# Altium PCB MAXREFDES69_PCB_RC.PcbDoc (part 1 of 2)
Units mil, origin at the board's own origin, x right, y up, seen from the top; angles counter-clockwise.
Board outline 2598.42 x 2244.09 mil, 6 copper layers (Top Layer, Mid-Layer 1, Mid-Layer 2, Mid-Layer 3, Mid-Layer 4, Bottom Layer); 103 components, 84 nets, 415 pads, 171 vias.
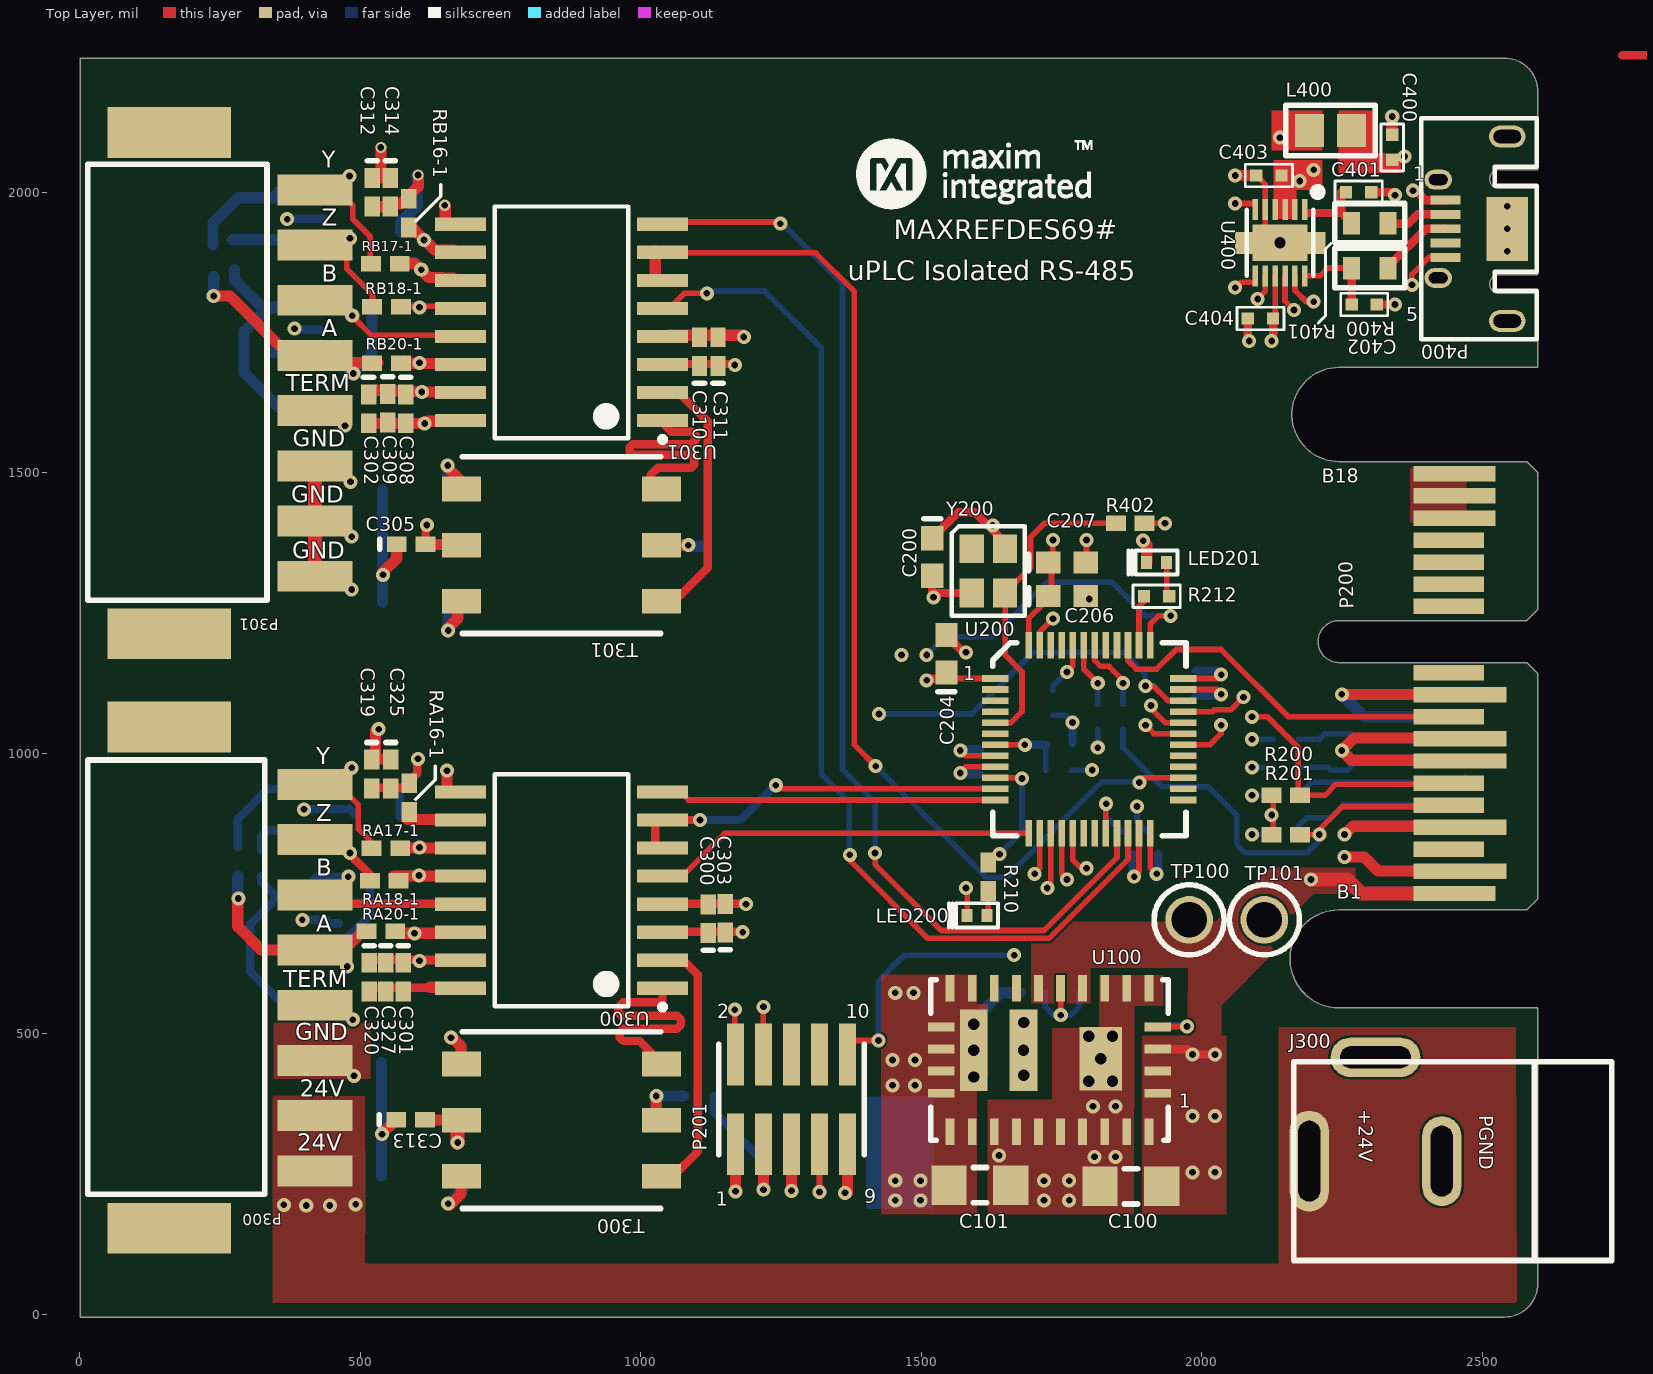
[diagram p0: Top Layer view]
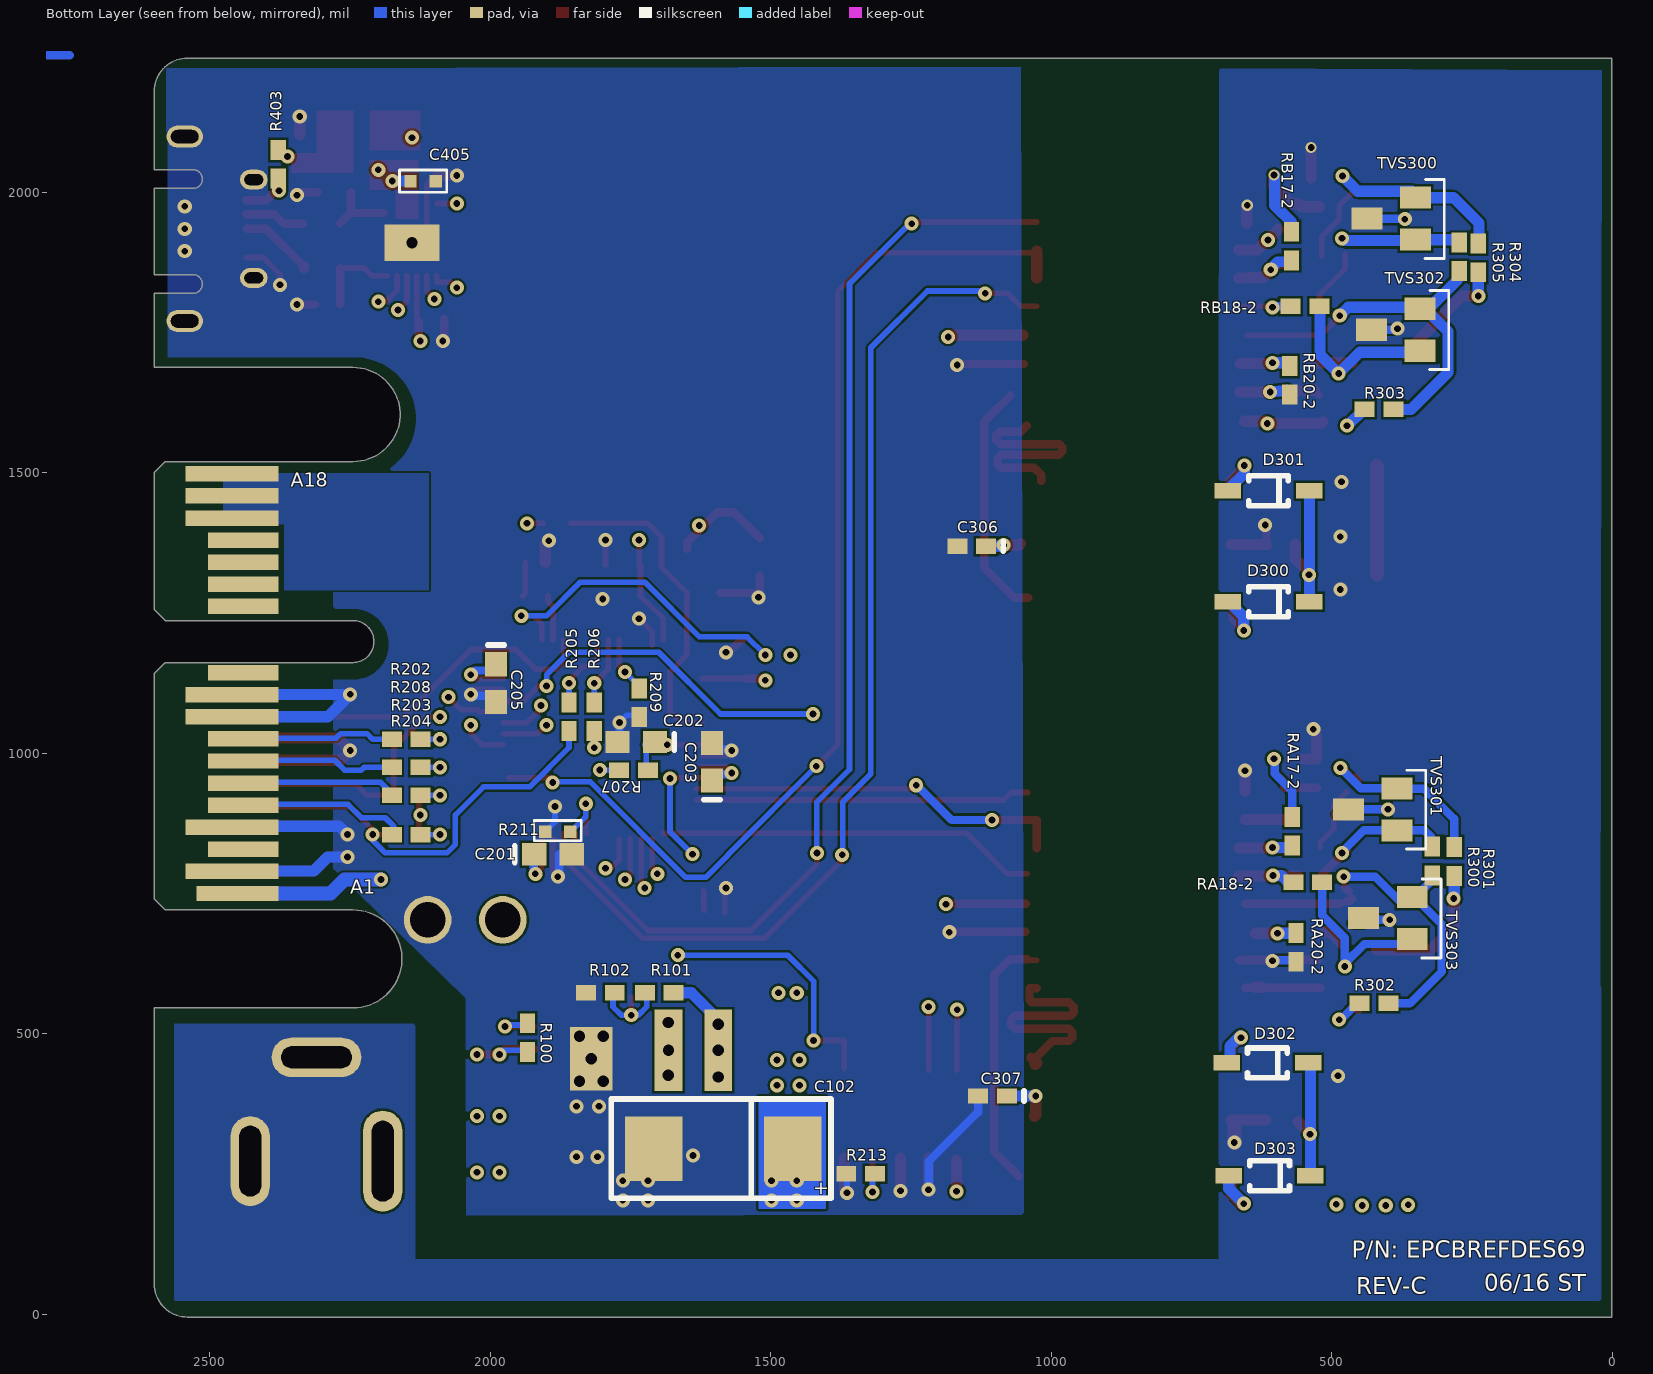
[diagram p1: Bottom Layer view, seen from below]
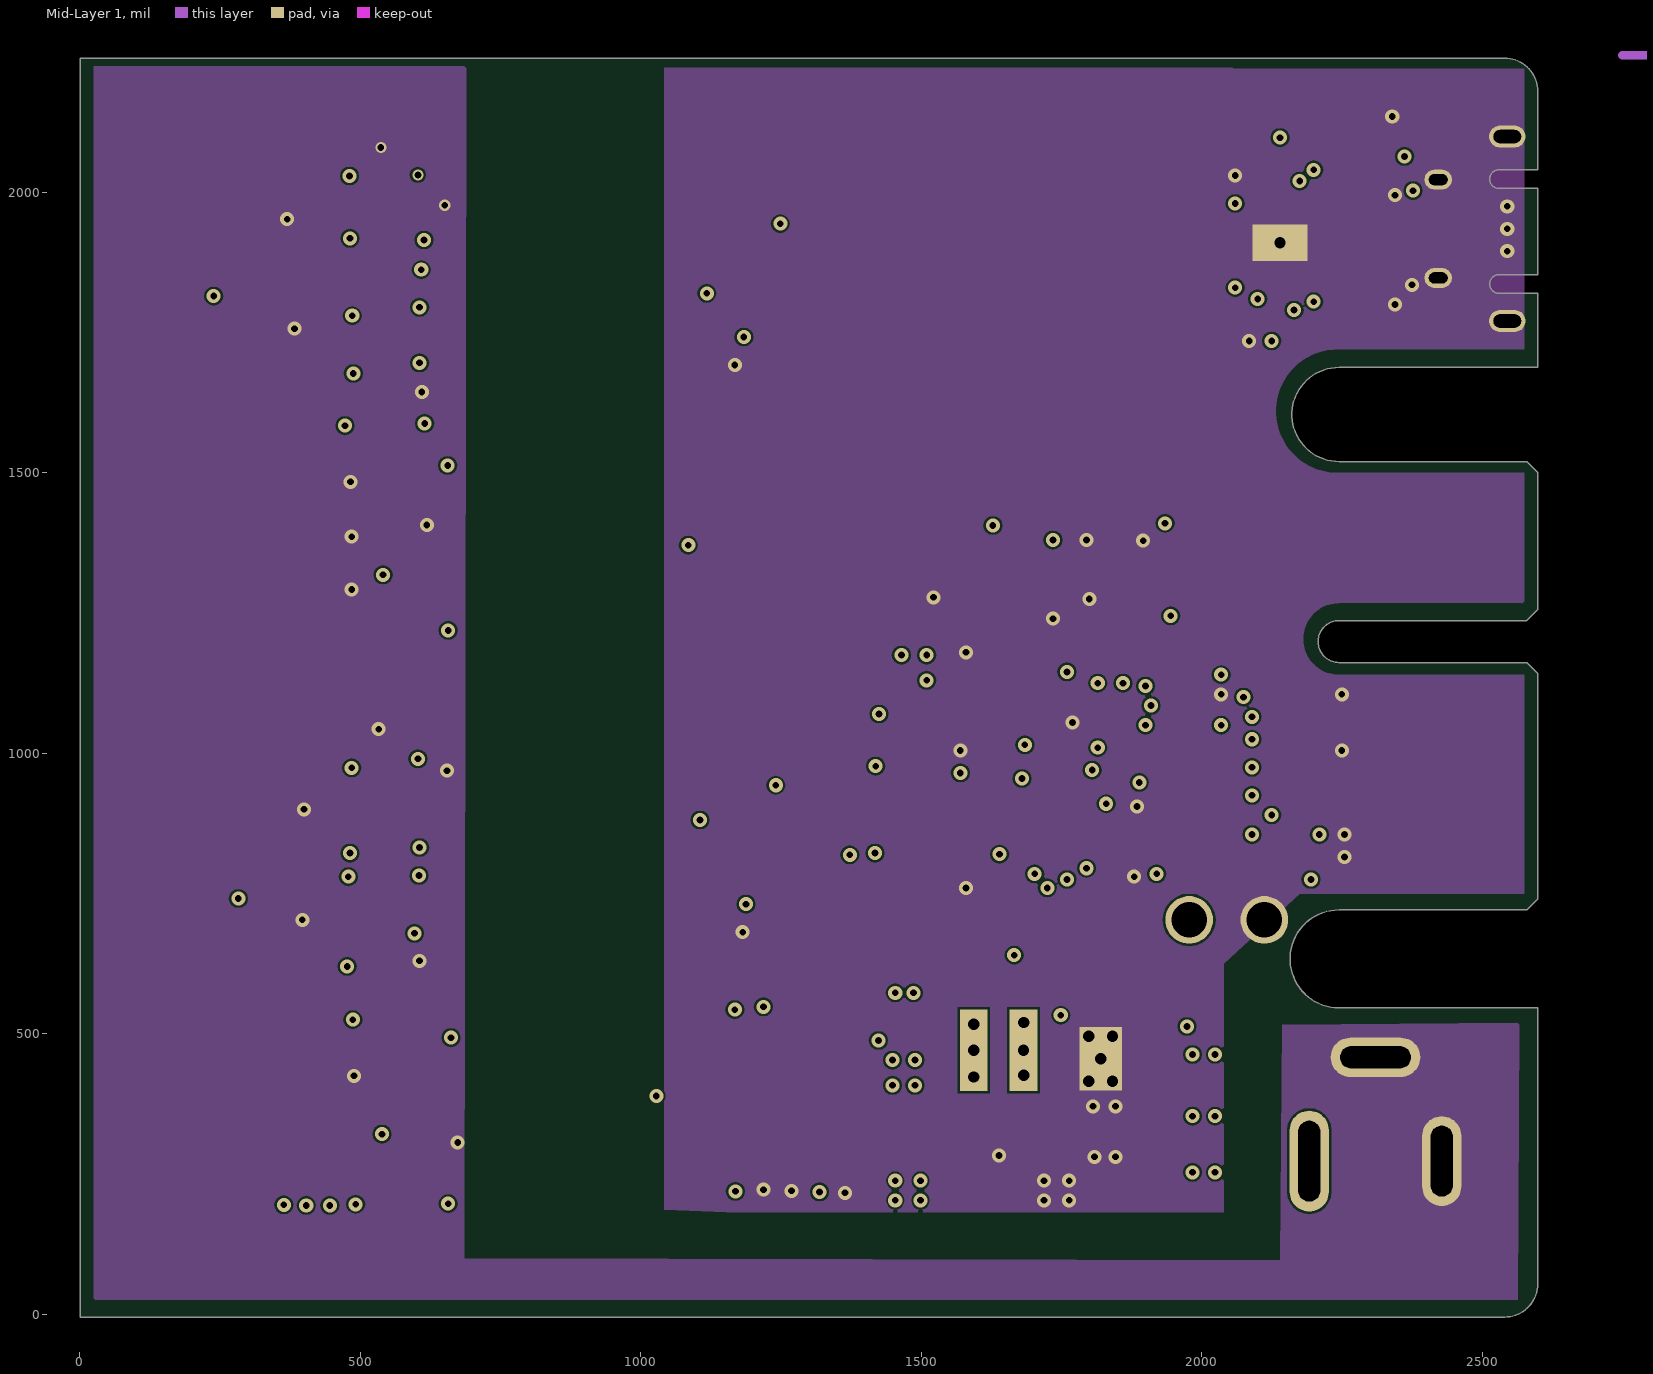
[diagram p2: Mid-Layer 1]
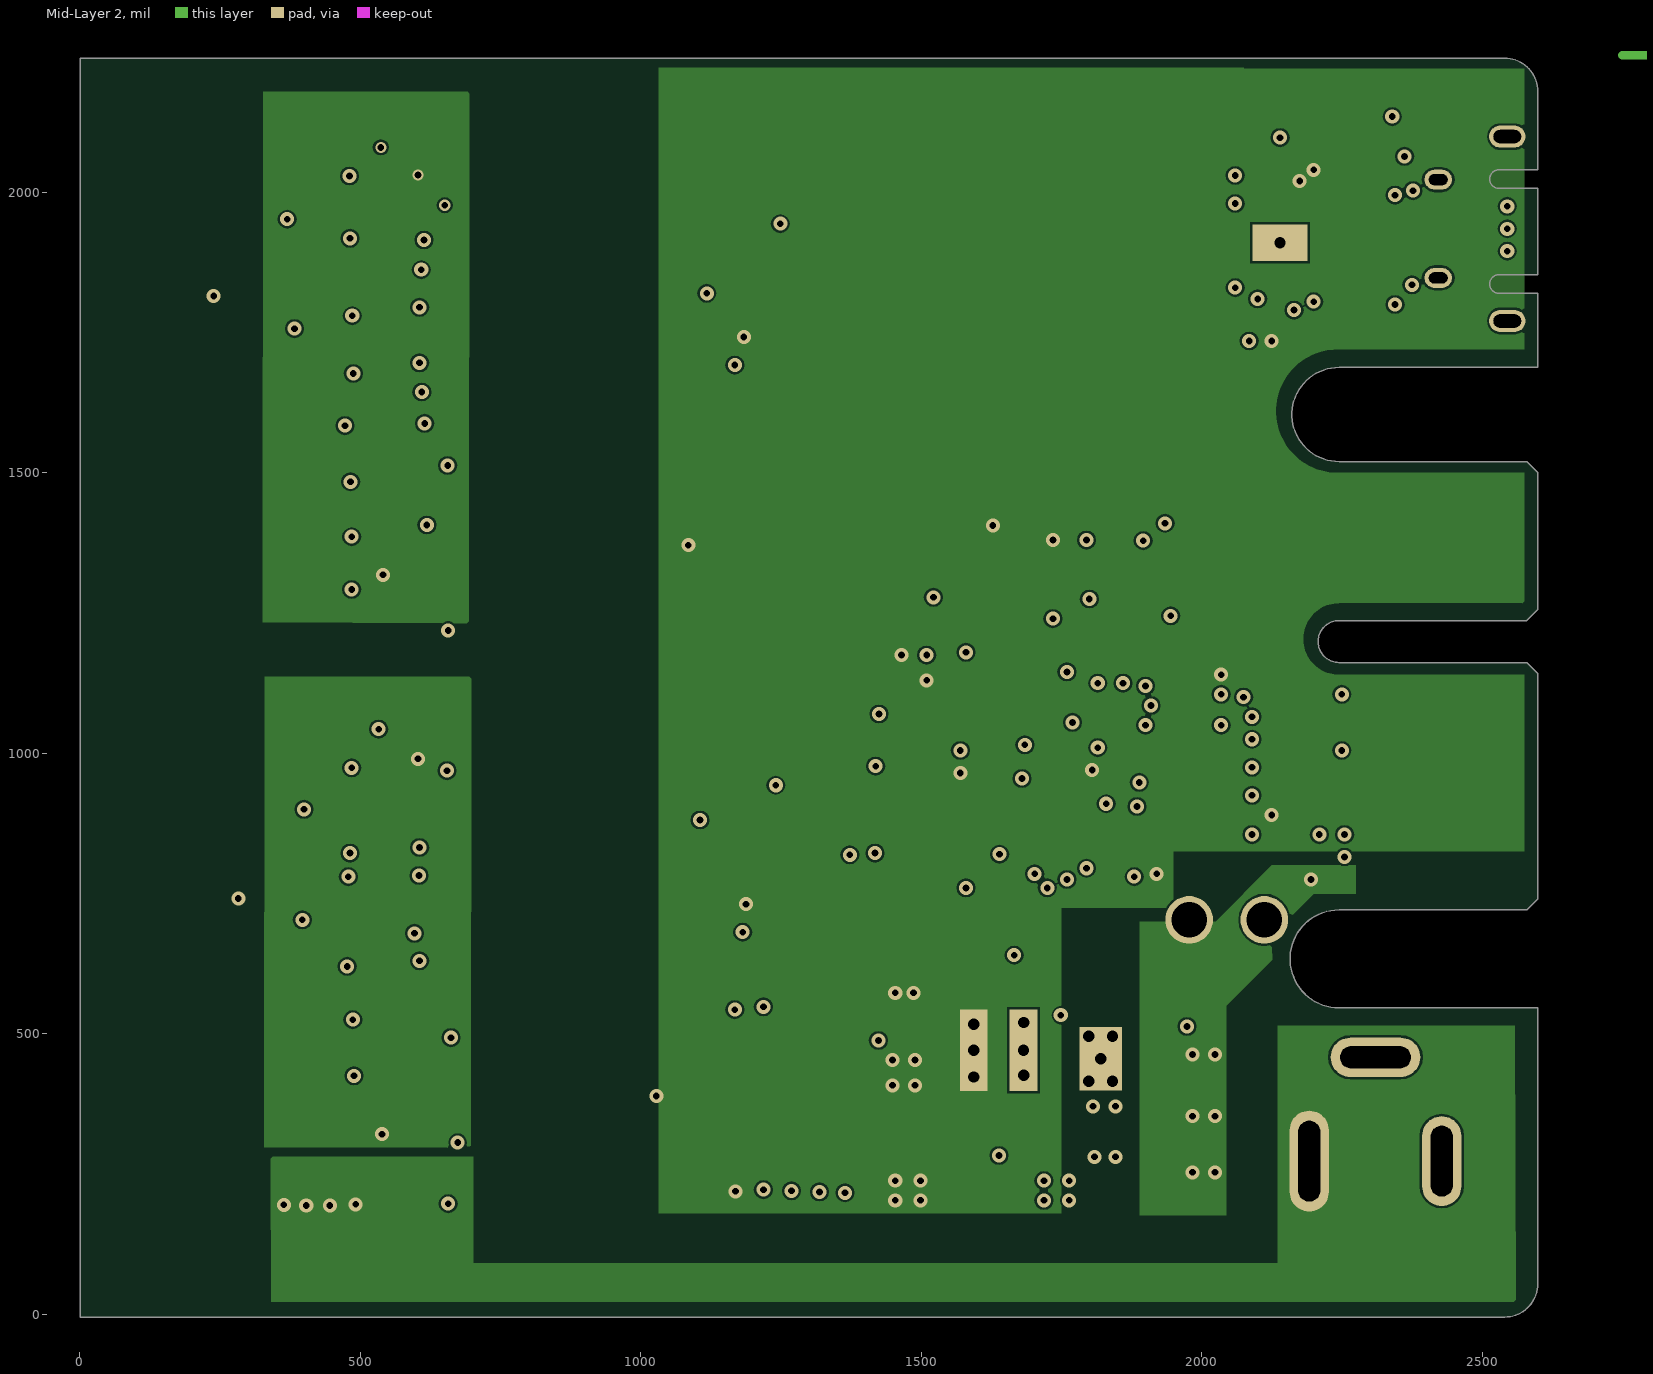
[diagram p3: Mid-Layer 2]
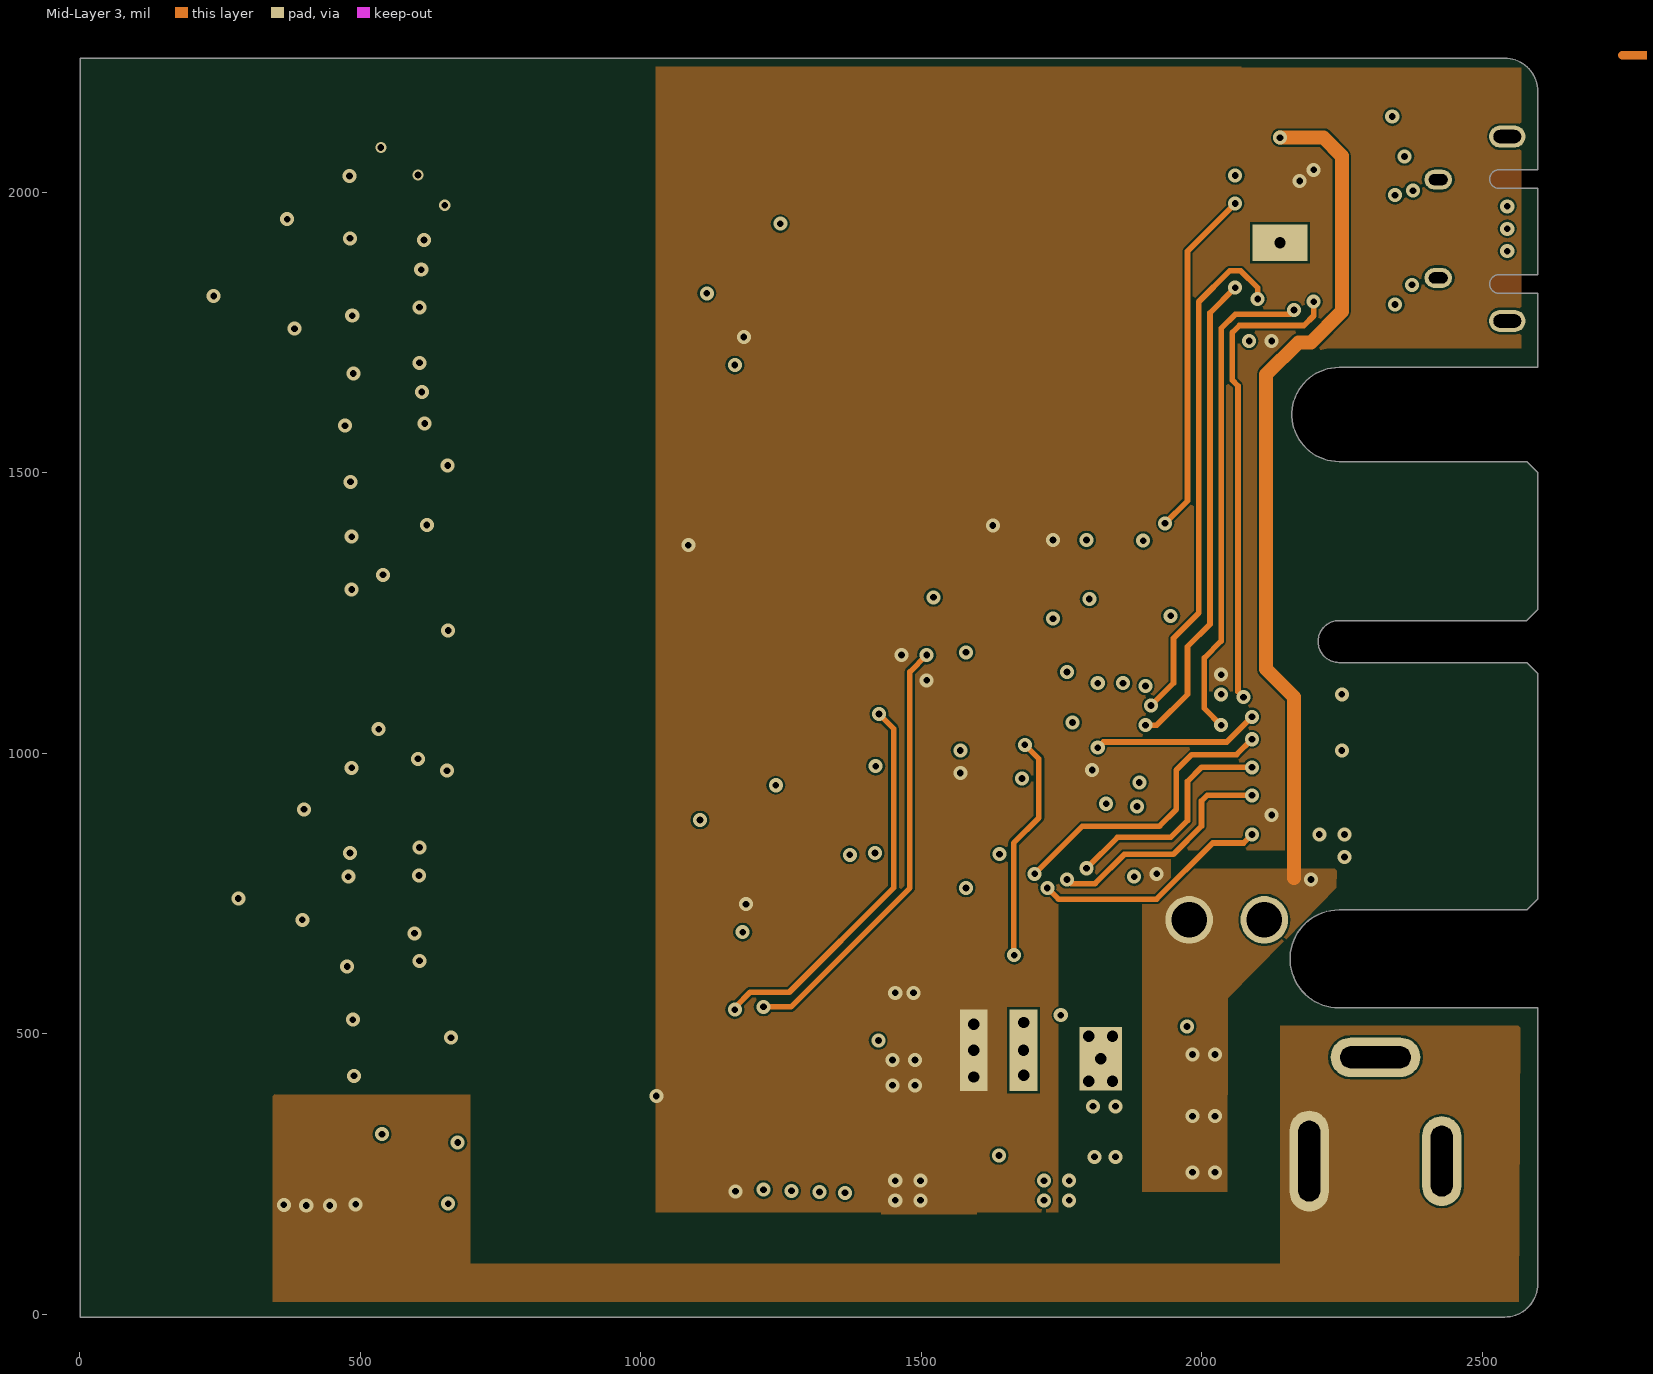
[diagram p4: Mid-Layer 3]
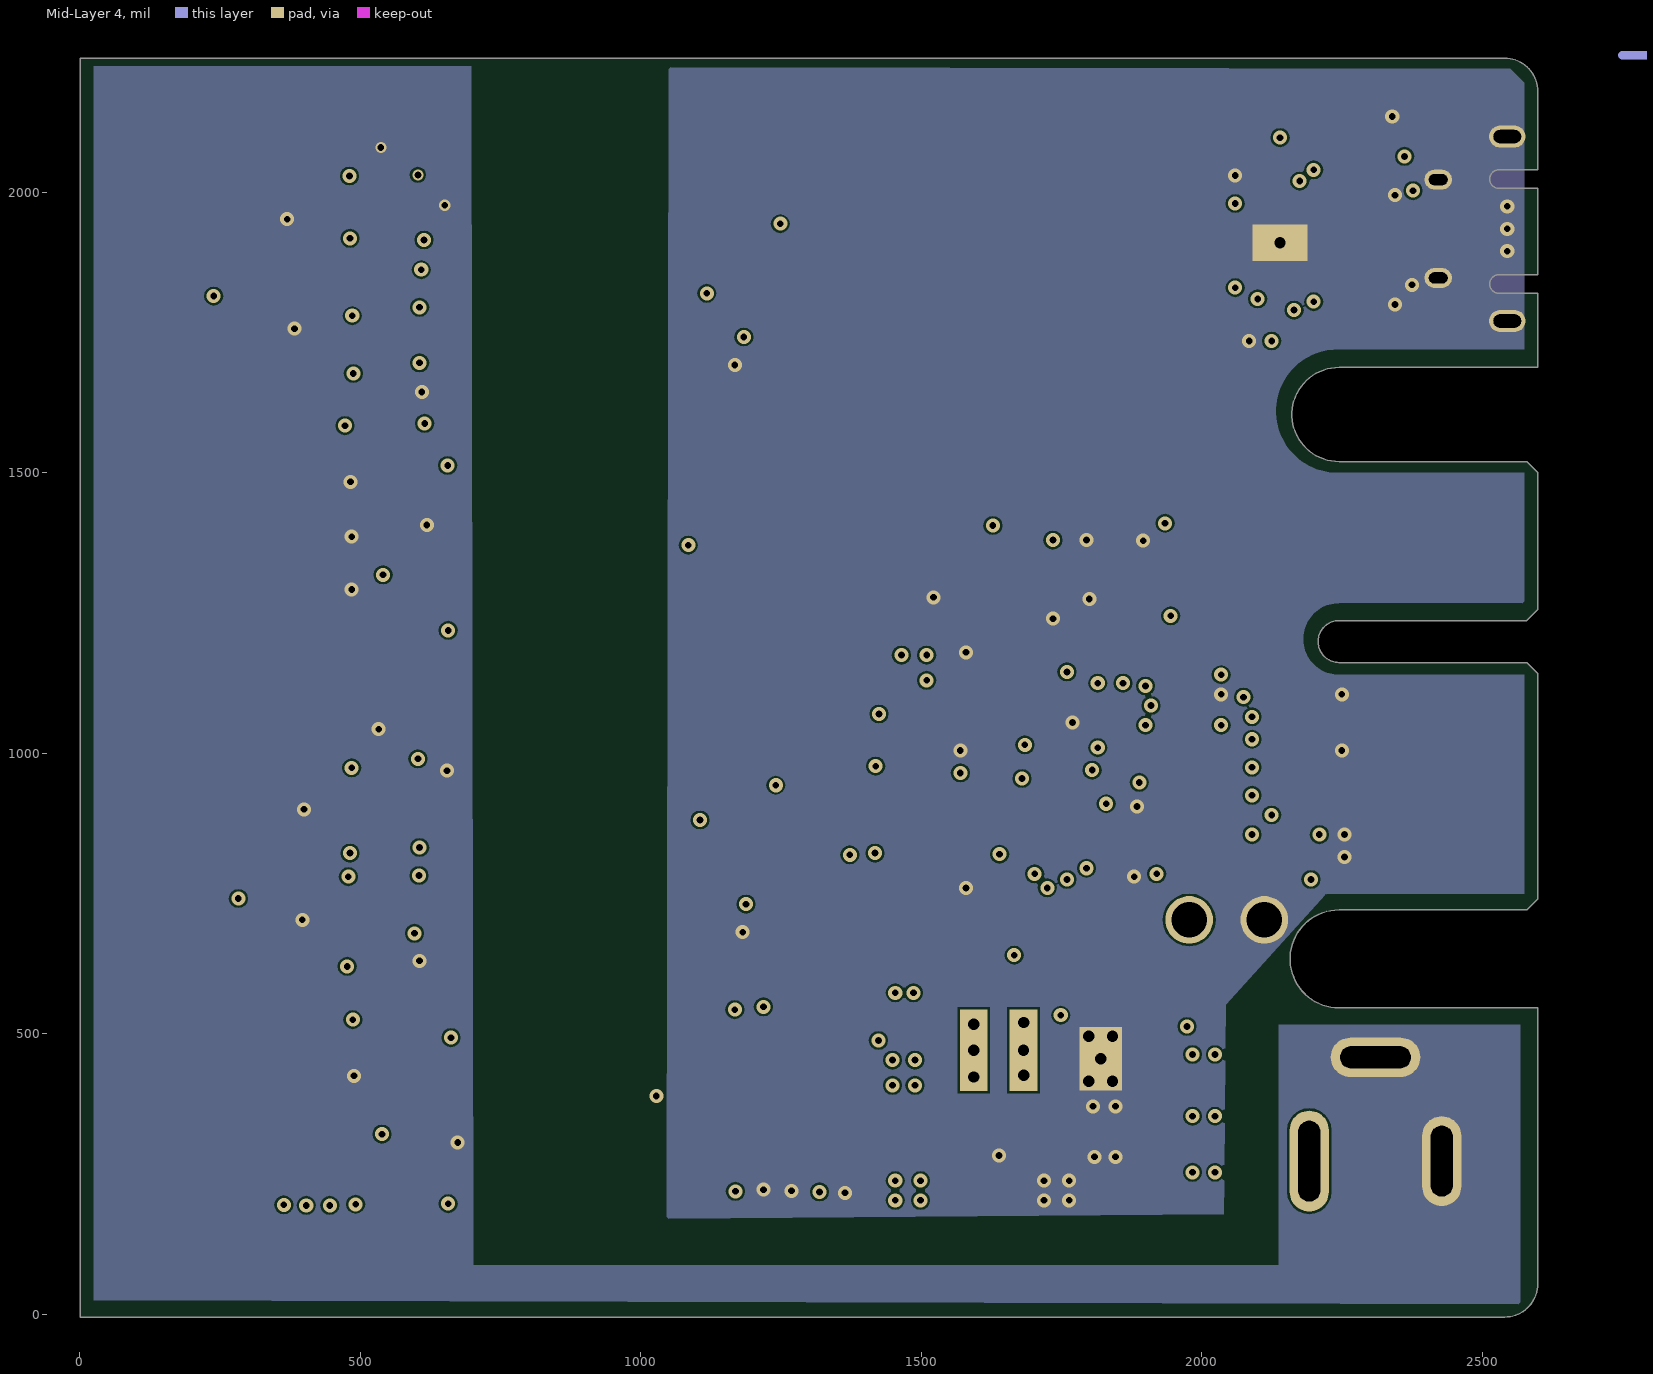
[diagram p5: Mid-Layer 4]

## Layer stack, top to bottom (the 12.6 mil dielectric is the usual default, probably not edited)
Top Layer: signal copper 1.4
Dielectric: dielectric 12.6, FR-4, Dk 4.8
Mid-Layer 1: signal copper 1.4
Dielectric: dielectric 12.6, FR-4, Dk 4.8
Mid-Layer 2: signal copper 1.4
Dielectric: dielectric 12.6, FR-4, Dk 4.8
Mid-Layer 3: signal copper 1.4
Dielectric: dielectric 12.6, FR-4, Dk 4.8
Mid-Layer 4: signal copper 1.4
Dielectric: dielectric 12.6, FR-4, Dk 4.8
Bottom Layer: signal copper 1.4

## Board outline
2245.1,546.18 cw(c2245.1,633.47) 2245.1,720.75 2579.74,720.75 2599.42,740.43 2599.42,1142.01 2579.74,1161.69 2245.09,1161.69 cw(c2245.09,1199.09) 2245.09,1236.49 2579.74,1236.49 2599.42,1256.18 2599.42,1500.27 2579.74,1519.96 2245.1,1519.96 cw(c2245.1,1603.94) 2245.1,1687.91 2599.42,1687.91 2599.42,1819.8 2530.53,1819.8 cw(c2530.33,1836.53) 2530.53,1853.27 2599.42,1853.27 2599.42,2006.81 2530.53,2006.81 2530.52,2006.81 cw(c2530.32,2023.54) 2530.52,2040.27 2530.53,2040.27 2599.42,2040.27 2599.42,2180.03 ccw(c2540.37,2180.03) 2540.37,2239.09 1,2239.09 1,-5 2540.37,-5 ccw(c2540.37,54.06) 2599.42,54.06 2599.42,546.18

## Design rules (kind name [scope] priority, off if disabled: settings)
AssemblyTestPointUsage [All] p1 off:
AssemblyTestpoint [All] p1 off: testpointundercomponent=TRUE minsize=40 maxsize=100 preferedsize=60 minholesize=0 maxholesize=40 preferedholesize=32 testpointgrid=1 usegrid=TRUE gridtolerance=0.01 allowsidetop=TRUE allowsidebottom=TRUE
Clearance [All] p1: gap=4
ComponentClearance [All] p1 off: gap=10 collisioncheckmode=3 verticalgap=10 showdistances=FALSE
DiffPairsRouting [All] p1 off: maxlimit=10 minlimit=10 mostfreqgap=10 maxuncoupledlength=500
FabricationTestPointUsage [All] p1 off: valid=0 allowmultiple=FALSE
FabricationTestpoint [All] p1 off: side=3 testpointundercomponent=TRUE minsize=40 maxsize=100 preferedsize=60 minholesize=0 maxholesize=40 preferedholesize=32 testpointgrid=1 allowsidetop=TRUE allowsidebottom=TRUE usegrid=TRUE gridtolerance=0.01
FanoutControl Fanout_BGA [IsBGA] p1 off: bgadir=Out bgaviamode=Centered fanoutstyle=Auto fanoutdirection=Alternating viagrid=1 // Fanout_BGA (Default Rule)
FanoutControl Fanout_LCC [IsLCC] p2 off: bgadir=Out bgaviamode=Centered fanoutstyle=Auto fanoutdirection=Alternating viagrid=1 // Fanout_LCC (Default Rule)
FanoutControl Fanout_SOIC [IsSOIC] p3 off: bgadir=Out bgaviamode=Centered fanoutstyle=Auto fanoutdirection=Alternating viagrid=1 // Fanout_SOIC (Default Rule)
FanoutControl Fanout_Small [(CompPinCount < 5)] p4 off: bgadir=Out bgaviamode=Centered fanoutstyle=Auto fanoutdirection=OutThenIn viagrid=1 // Fanout_Small (Default Rule)
FanoutControl Fanout_Default [All] p5 off: bgadir=Out bgaviamode=Centered fanoutstyle=Auto fanoutdirection=Alternating viagrid=1 // Fanout_Default (Default Rule)
FlightTimeFalling "'Default' PADS rule_10" [All] p1 off: maximum=10.00
FlightTimeRising "'Default' PADS rule_9" [All] p1 off: maximum=10.00
Height [All] p1 off: minheight=0 maxheight=1000 prefheight=500
HoleSize [All] p1: absolutevalues=TRUE maxlimit=150 minlimit=1 maxpercent=80.000 minpercent=20.000
HoleToHoleClearance [All] p1: gap=3 allowstackedmicrovias=TRUE
Length "'Default' PADS rule_5" [All] p1 off: maxlimit=50000 minlimit=0
MatchedLengths "'Default' PADS rule_11" [InNetClass('All Nets')] p1 off: tolerance=200 checknetsindiffpair=TRUE checkdiffpairvsdiffpair=TRUE checkothers=FALSE
MaxMinImpedance "'Default' PADS rule_8" [All] p1 off: minimum=50.00 maximum=150.0
MinimumSolderMaskSliver [All] p1: minsoldermaskwidth=0
ParallelSegment "'Default' PADS rule_7" [All] p1 off: limit=1000 gap=200
ParallelSegment "'Default' PADS rule_6" [All] p2 off: limit=1000 gap=10
PasteMaskExpansion [All] p1: expansion=2
PlaneConnect "Power Plane Connect Style - from global settings" [All] p1: planeconnectstyle=Direct reliefexpansion=20 reliefentries=4 reliefconductorwidth=25 reliefairgap=10
PolygonConnect [All] p1: connectstyle=Direct reliefconductorwidth=10 reliefentries=4 polygonreliefangle="90 Angle"
RoutingTopology [All] p1 off: topology=Shortest
RoutingVias [All] p1: holewidth=28 width=50 viastyle="Through Hole" minholewidth=5 minwidth=10 maxholewidth=28 maxwidth=50
SilkToSilkClearance [All] p1 off: silktosilkclearance=10
SilkscreenOverComponentPads [All] p1 off: minsilkscreentomaskgap=0
SolderMaskExpansion "Solder Mask Expansion from CAM settings" [All] p1: expansion=3
Width "'Default' PADS rule_13" [All] p1 off: maxlimit=100 minlimit=5 preferedwidth=10
8 further rules are at their usual default settings.

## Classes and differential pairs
component class "RS485 Comm Board Power 3r0": C100 C101 C102 R100 R101 R102 TP100 TP101 U100
component class "RS485 Comm Board Processor 3r0": C200 C201 C202 C203 C204 C205 C206 C207 LED200 LED201 NT201 P200 P201 R200 R201 R202 R203 R204 R205 R206 R207 R208 R209 R210 R211 R212 R213 TP200 TP201 U200 Y200
component class "RS485 Comm Board 3r0": C300 C301 C302 C303 C305 C306 C307 C308 C309 C310 C311 C312 C313 C314 C319 C320 C325 C327 D300 D301 D302 D303 J300 P300 P301 R300 R301 R302 R303 R304 R305 RA16-1 RA17-1 RA17-2 RA18-1 RA20-1 RB16-1 RB17-2 RB18-1 RB20-1 T300 T301 TVS300 TVS301 TVS302 TVS303 U300 U301
component class "RS485 Generic USB 3r0": C400 C401 C402 C403 C404 C405 L400 P400 R400 R401 R402 R403 U400

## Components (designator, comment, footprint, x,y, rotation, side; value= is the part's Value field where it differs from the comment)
C100 "CAP" 1206 1874,228 r180 top
C101 "CAP" 1206 1605,230 r0 top
C102 "CAP" CAP\PANA\TPE\D2E 1585,295 r270 bottom
C200 "CAP" 0603 1520,1350 r270 top
C201 "CAP" 0603 1888.58,820 r180 bottom
C202 "CAP" 0603 1740,1020 r0 bottom
C203 "CAP" 0603 1605,985 r90 bottom
C204 "CAP" 0603 1545,1177.5 r90 top
C205 "CAP" 0603 1990,1125 r270 bottom
C206 "CAP" 0603 1760,1280 r0 top
C207 "CAP" 0603 1760,1340 r0 top
C300 "CAP" 0402 1121,705 r90 top
C301 "CAP" 0402 577,601 r270 top
C302 "CAP" 0402 515,1614 r270 top
C303 "CAP" 0402 1151,706 r90 top
C305 "CAP" 0402 591,1373 r0 top
C306 "CAP" 0402 1142,1369 r0 bottom
C307 "CAP" 0402 1105,389 r0 bottom
C308 "CAP" 0402 581,1614 r270 top
C309 "CAP" 0402 549,1615 r270 top
C310 "CAP" 0402 1105,1716 r90 top
C311 "CAP" 0402 1138,1716 r90 top
C312 "CAP" 0402 522,2000 r270 top
C313 "CAP" 0402 590,347 r0 top
C314 "CAP" 0402 554,2000 r270 top
C319 "CAP" 0402 521,963 r270 top
C320 "CAP" 0402 516,601 r270 top
C325 "CAP" 0402 555,963 r270 top
C327 "CAP" 0402 546,601 r270 top
C400 "CAP" CC0402 2340,2080 r90 top
C401 "CAP" CC0402 2280,2000 r0 top
C402 "CAP" CC0402 2290,1800 r0 top
C403 "CAP" CC0402 2120,2030 r180 top
C404 "CAP" CC0402 2105,1775 r180 top
C405 "CAP" CC0402 2120,2020 r180 bottom
D300 "DIODE_SCHOTTKY" SOD123 613,1270 r180 bottom
D301 "DIODE_SCHOTTKY" SOD123 613,1468 r180 bottom
D302 "DIODE_SCHOTTKY" SOD123 615,448 r180 bottom
D303 "DIODE_SCHOTTKY" SOD123 611,247 r180 bottom
J300 "DC Power Jack 24V 1A" JACK\CUI\PJ-202AH 2192.01,272.99 r0 top locked
L400 "Ferrite Bead" R0805 2230,2110 r180 top
LED200 "LED" LED\ROHM\SML-P1 1600,711 r270 top
LED201 "LED" LED\ROHM\SML-P1 1920,1340 r270 top
P200 "CON_PCIE_1_CARD_EDGE" CONN\PCI_EXP\36P\CARDEDGE\GLPMSS 2598.43,750 r90 top locked
P201 "HEADER 5X2" CONN\SAMTEC\FTSH-105-01-L-DV-K 1269,383 r90 top locked
P300 "CON8" TB\8POS\PHOENIXCONTACT\1771088 160,600 r270 top locked
P301 "CON8" TB\8POS\PHOENIXCONTACT\1771088 160,1660 r270 top locked
P400 "CONN\HIROSE\ZX62RD-AB-5P8\MICRO_AB" CONN\HIROSE\ZX62RD-AB-5P8\MICRO_AB 2545,1935 r90 top locked
R100 "RES1" R0402 1934,493 r270 bottom
R101 "RES1" R0402 1699,573 r180 bottom
R102 "RES1" R0402 1804,573 r180 bottom
R200 "RES1" R0402 2150,925 r180 top
R201 "RES1" R0402 2150,855 r180 top
R202 "RES1" R0402 2150,1025 r180 bottom
R203 "RES1" R0402 2150,925 r180 bottom
R204 "RES1" R0402 2150,855 r180 bottom
R205 "RES1" R0402 1860,1065 r90 bottom
R206 "RES1" R0402 1815,1065 r90 bottom
R207 "RES1" R0402 1745,970 r0 bottom
R208 "RES1" R0402 2150,975 r180 bottom
R209 "RES1" R0402 1735,1090 r90 bottom
R210 "RES1" R0402 1620,780 r90 top
R211 "CC0402" CC0402 1880,860 r180 bottom
R212 "RES1" CC0402 1920,1280 r180 top
R213 "RES1" R0402 1340.13,250.78 r180 bottom
R300 "RES1" R0402 321,808 r90 bottom
R301 "RES1" R0402 282,807 r90 bottom
R302 "RES1" R0402 425,554 r180 bottom
R303 "RES1" R0402 416,1613 r180 bottom
R304 "RES1" R0402 239,1883 r90 bottom
R305 "RES1" R0402 273,1885 r90 bottom
R400 "RES1" CC0603 2300,1865 r180 top
R401 "RES1" CC0603 2300,1945 r180 top
R402 "RES1" R0402 1873,1410 r180 top
R403 "RES1" R0402 2378,2050 r90 bottom
RA16-1 "RES1" R0402 588,921 r90 top
RA17-1 "RES1" R0402 546,831 r180 top
RA17-2 "RES1" R0402 571,861 r90 bottom
RA18-1 "RES1" R0402 543,773 r180 top
RA18-2 "RES1" R0402 543,770 r180 bottom
RA20-1 "RES1" R0402 537,683 r180 top
RA20-2 "RES1" R0402 564,654 r270 bottom
RB16-1 "RES1" R0402 587,1963 r90 top
RB17-1 "RES1" R0402 545,1873 r180 top
RB17-2 "RES1" R0402 572,1904 r90 bottom
RB18-1 "RES1" R0402 547,1796 r180 top
RB18-2 "RES1" R0402 548,1797 r180 bottom
RB20-1 "RES1" R0402 547,1695 r180 top
RB20-2 "RES1" R0402 575,1665 r270 bottom
T300 "Transformer" "XFMR (WURTH 750315225)" 859,346 r180 top locked
T301 "Transformer" "XFMR (WURTH 750315225)" 859,1371 r180 top locked
TP100 "RED" TestPoint 1978,703 r90 top
TP101 "BLK" TestPoint 2112,703 r90 top
TVS300 "TVS SM712" "SM712 TVS" 394,1953 r90 bottom
TVS301 "TVS SM712" "SM712 TVS" 427,900 r90 bottom
TVS302 "TVS SM712" "SM712 TVS" 386,1755 r90 bottom
TVS303 "TVS SM712" "SM712 TVS" 400,706 r90 bottom
U100 "MAX17515" SIP28\LGA\6.5X10MM\28L\3EP\L286510+1 1729,453 r270 top locked
U200 "STM32F103CB" "LQFP48 - ST Micro" 1800,1025 r0 top locked
U300 "ISO-RS485" "SOIC 16W(W16M-9/10)" 859,756 r180 top
U301 "ISO-RS485" "SOIC 16W(W16M-9/10)" 859,1768 r180 top
U400 "FT234XD" DFN\3X3MM\12L\EP 2140,1910 r270 top
Y200 "OSC KYOCERA" XTAL\HOSONIC\2520 1620,1325 r270 top

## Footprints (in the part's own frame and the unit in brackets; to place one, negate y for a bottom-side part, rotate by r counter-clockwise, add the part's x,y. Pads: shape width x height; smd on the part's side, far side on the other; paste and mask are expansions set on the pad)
0402 [mm] "1.0 x 0.5 mm (LxW typ)"
  rect 0.9x0.7 smd: 1(-0.65,0) 2(0.65,0)
  silkscreen extent -1.43,-0.22 -1.43,0.23, body extent -0.5,-0.25 0.5,0.25, height 1
0603 [mm] "Chip Resistor; Body 1.6 x 0.9 mm (LxW typ)"
  rect 1.1x1 smd: 1(-0.85,0) 2(0.85,0)
  silkscreen extent -1.73,-0.37 -1.73,0.38, body extent -0.85,-0.45 0.85,0.45, height 1
1206 [mm]
  rect 1.6x1.8 smd: 1(-1.4,0) 2(1.4,0)
  silkscreen extent -0.3,-0.8 0.3,0.8, body extent -1.7,-0.9 1.7,0.9, height 2
CAP\PANA\TPE\D2E [mm]
  rect 2.9x2.6 smd: 1(0,3.15) 2(0,-3.15)
  silkscreen extent -2.25,-5.08 2.25,4.88
CC0402 [mil]
  rect 22x22 smd: 1(-22.5,0) 2(22.5,0)
  silkscreen extent -42,-20 42,20
CC0603 [mil]
  rect 30x40 smd: 1(-32.5,0) 2(32.5,0)
  silkscreen extent -63,-35 63,35
CONN\HIROSE\ZX62RD-AB-5P8\MICRO_AB [mm]
  rect 0.4x1.35 smd: 1(1.3,2.8) 2(0.65,2.8) 3(0,2.8) 4(-0.65,2.8) 5(-1.3,2.8)
  rect 2.9x1.9 smd: 6(0,0)
  oval 1x1.65 hole 0.6 slot 1.25 at 90 deg: 7(4.175,0) 8(-4.175,0)
  oval 0.9x1.25 hole 0.5 slot 0.85 at 90 deg: 9(2.225,3.125) 10(-2.225,3.125)
  Top Layer pour cut-out: -3.8,2 -3.8,1.125 -3.6,1.125 -3.6,-1.075 -3,-1.075 -3,0.762 -1.8,0.762 -1.8,-1.075 -1.5,-1.075 -1.5,1.025 1.5,1.025 1.5,-1.075 1.8,-1.075 1.8,0.762 2.977,0.762 2.977,-1.1 3.572,-1.1 3.572,1.125 3.7,1.125 3.7,2 2,2 2,1.75 -2,1.75 -2,2
  silkscreen extent -5,-1.33 5,3.9
CONN\PCI_EXP\36P\CARDEDGE\GLPMSS [mm]
  rect 0.7x3.7 smd far side: A1(0,3.75)
  rect 0.7x4.2 smd far side: A2(1,3.5) A4(3,3.5) A9(8,3.5) A10(9,3.5) A16(17,3.5) A17(18,3.5) A18(19,3.5)
  rect 0.7x3.2 smd far side: A3(2,4) A5(4,4) A6(5,4) A7(6,4) A8(7,4) A11(10,4) A12(13,4) A13(14,4) A14(15,4) A15(16,4)
  rect 0.7x3.7 smd: B1(0,3.75) B16(17,3.75) B17(18,3.75) B18(19,3.75)
  rect 0.7x4.2 smd: B2(1,3.5) B4(3,3.5) B7(6,3.5) B8(7,3.5) B10(9,3.5)
  rect 0.7x3.2 smd: B3(2,4) B5(4,4) B6(5,4) B9(8,4) B11(10,4) B12(13,4) B13(14,4) B14(15,4) B15(16,4)
CONN\SAMTEC\FTSH-105-01-L-DV-K [mil]
  rect 110x30 smd: 1(-80,100) 2(80,100) 3(-80,50) 4(80,50) 5(-80,0) 6(80,0) 7(-80,-50) 8(80,-50) 9(-80,-100) 10(80,-100)
  silkscreen extent -98,-130 98,130
DFN\3X3MM\12L\EP [mm]
  rect 0.95x0.25 smd: 1(-1.5,1.125) 2(-1.5,0.675) 3(-1.5,0.225) 4(-1.5,-0.225) 5(-1.5,-0.675) 6(-1.5,-1.125) 7(1.5,-1.125) 8(1.5,-0.675) 9(1.5,-0.225) 10(1.5,0.225) 11(1.5,0.675) 12(1.5,1.125)
  rect 1.65x2.5 smd: 13(0,0)
  round 1.016 / inner rect 1.65x2.5 / far side rect 1.65x2.5 hole 0.508: 14(0,0)
  rect 1x1 smd: 15(0,1.55) 16(0,-1.55)
  silkscreen extent -2.41,-1.5 1.5,1.81
JACK\CUI\PJ-202AH [mil]
  oval 70x180 hole 39.37 slot 143.7 at 90 deg: 1(0,0)
  oval 70x160 hole 39.37 slot 125.98 at 90 deg: 2(236.22,0)
  oval 160x70 hole 39.37 slot 125.98 at 0 deg: 3(118.11,185.04)
  silkscreen extent -28,-177 539,177
LED\ROHM\SML-P1 [mm]
  rect 0.6x0.5 smd: 1(0,0.45) 2(0,-0.45)
  silkscreen extent -0.55,-1.27 0.55,0.95
"LQFP48 - ST Micro" [mm] "LQFP48 - 7x7 ST Micro"
  rect 1.2x0.3 smd: 1(-4.25,2.75) 2(-4.25,2.25) 3(-4.25,1.75) 4(-4.25,1.25) 5(-4.25,0.75) 6(-4.25,0.25) 7(-4.25,-0.25) 8(-4.25,-0.75) 9(-4.25,-1.25) 10(-4.25,-1.75) 11(-4.25,-2.25) 12(-4.25,-2.75) 25(4.25,-2.75) 26(4.25,-2.25) 27(4.25,-1.75) 28(4.25,-1.25) 29(4.25,-0.75) 30(4.25,-0.25) 31(4.25,0.25) 32(4.25,0.75) 33(4.25,1.25) 34(4.25,1.75) 35(4.25,2.25) 36(4.25,2.75)
  rect 0.3x1.2 smd: 13(-2.75,-4.25) 14(-2.25,-4.25) 15(-1.75,-4.25) 16(-1.25,-4.25) 17(-0.75,-4.25) 18(-0.25,-4.25) 19(0.25,-4.25) 20(0.75,-4.25) 21(1.25,-4.25) 22(1.75,-4.25) 23(2.25,-4.25) 24(2.75,-4.25) 37(2.75,4.25) 38(2.25,4.25) 39(1.75,4.25) 40(1.25,4.25) 41(0.75,4.25) 42(0.25,4.25) 43(-0.25,4.25) 44(-0.75,4.25) 45(-1.25,4.25) 46(-1.75,4.25) 47(-2.25,4.25) 48(-2.75,4.25)
  silkscreen extent -4.38,-4.38 4.38,4.38
R0402 [mm] "Chip Resistor; Body 1.1 x 0.5 mm (LxW typ)"
  rect 0.9x0.7 smd: 1(-0.65,0) 2(0.65,0)
  body extent -0.5,-0.25 0.5,0.25, height 1
R0805 [mm] "Chip Resistor; Body 2 x 1.2 mm (LxW typ)"
  rect 1.3x1.5 smd: 1(-0.95,0) 2(0.95,0)
  silkscreen extent -2.03,-1.14 2.03,1.14, body extent -1.1,-0.72 1.1,0.72, height 1
SIP28\LGA\6.5X10MM\28L\3EP\L286510+1 [mm]
  rect 0.4x1.2 smd: 1(1.5,4.9) 2(0.5,4.9) 3(-0.5,4.9) 4(-1.5,4.9) 15(-1.5,-4.9) 16(-0.5,-4.9) 17(0.5,-4.9) 18(1.5,-4.9)
  rect 1.2x0.4 smd: 5(-3.25,4.5) 6(-3.25,3.5) 7(-3.25,2.5) 8(-3.25,1.5) 9(-3.25,0.5) 10(-3.25,-0.5) 11(-3.25,-1.5) 12(-3.25,-2.5) 13(-3.25,-3.5) 14(-3.25,-4.5) 19(3.25,-4.5) 20(3.25,-3.5) 21(3.25,-2.5) 22(3.25,-1.5) 23(3.25,-0.5) 24(3.25,0.5) 25(3.25,1.5) 26(3.25,2.5) 27(3.25,3.5) 28(3.25,4.5)
  rect 3.7x1.25 smd: 29(-0.45,-3.43) 30(-0.45,-1.18)
  rect 2.89x1.94 smd: 31(-0.06,2.32)
  round 0.762 / inner rect 3.7x1.25 / far side rect 3.7x1.25 hole 0.508: 32(-0.45,-3.43) 35(-0.45,-1.18)
  round 0.762 hole 0.508: 33(-1.626,-3.429) 34(0.762,-3.429) 36(-1.702,-1.168) 37(0.686,-1.168) 39(-1.08,2.857) 40(0.952,2.857) 41(-1.08,1.778) 42(0.952,1.778)
  round 0.762 / inner rect 2.89x1.94 / far side rect 2.89x1.94 hole 0.508: 38(-0.06,2.32)
  silkscreen extent -3.63,-5.38 3.63,5.38
"SM712 TVS" [mm]
  rect 1x1.4 smd: 1(0.95,-1.1) 2(-0.95,-1.1) 3(0,1.1)
  silkscreen extent -1.8,-2.4 1.78,-1.53
SOD123 [mm] "2-pin SOD-123"
  rect 1.2x0.7 smd: 1(-1.85,0) 2(1.85,0)
  silkscreen extent -0.9,-0.67 0.9,0.67
"SOIC 16W(W16M-9/10)" [mm]
  rect 2.3x0.6 smd: 1(-4.575,4.445) 2(-4.575,3.175) 3(-4.575,1.905) 4(-4.575,0.635) 5(-4.575,-0.635) 6(-4.575,-1.905) 7(-4.575,-3.175) 8(-4.575,-4.445) 9(4.575,-4.445) 10(4.575,-3.175) 11(4.575,-1.905) 12(4.575,-0.635) 13(4.575,0.635) 14(4.575,1.905) 15(4.575,3.175) 16(4.575,4.445)
  silkscreen extent -4.7,-5.25 3.03,5.42, body extent -3.8,-5.25 3.8,5.25, height 2.35
TB\8POS\PHOENIXCONTACT\1771088 [mm]
  rect 1.4x3.4 smd: 1(-8.75,6.6) 2(-6.25,6.6) 3(-3.75,6.6) 4(-1.25,6.6) 5(1.25,6.6) 6(3.75,6.6) 7(6.25,6.6) 8(8.75,6.6)
  rect 2.3x5.6 smd: 9(-11.35,0) 10(11.35,0)
  silkscreen extent -9.86,-3.7 9.8,4.32
TestPoint [mil] "Test Point Loop"
  round 85 hole 63: 1(0,0)
  silkscreen extent -62,-62 62,62
"XFMR (WURTH 750315225)" [mm]
  round 1 on Top Overlay: 1(-5,5)
  rect 1.77x1.12 smd: 1(-4.53,2.54) 2(-4.53,0) 3(-4.53,-2.54) 4(4.53,-2.54) 5(4.53,0) 6(4.53,2.54)
  silkscreen extent -4.5,-4 4.5,4
XTAL\HOSONIC\2520 [mm]
  rect 1.3x1.1 smd: 1(-1,-0.75) 2(1,-0.75) 3(1,0.75) 4(-1,0.75)
  silkscreen extent -2.03,-1.65 2.03,1.65

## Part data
C100 C101 C102 C200 C201 C202 C203 C204 C205 C206 C207 C300 C301 C302 C303 C305 C306 C307 C308 C309 C310 C311 C312 C313 C314 C319 C320 C325 C327 C400 C401 C402 C403 C404 C405: "Capacitor"
D300 D301 D302 D303: "Schottky Diode"
J300: "DC Power Jack 24V 5A - CUI PJ-202AH"
L400: library part Inductor, "Inductor"
P200: library part CON_PCIE_1_STATIC, "PCIE-1, FCI 10018783-10200TLF"
P300 P301: "Header, 8-pin"
P400: library part USB_MINI_B, "USB Micro B Connector"
R211: library part RES1
T300 T301: library part "Transformer (RU77)"
TP100 TP101: library part TESTPOINT, "Test Point Loop"
U200: "STM32F103 Micorprocessor"
U300 U301: library part ISO_RS485_Combo_1
U400: "USB - Serial, SSOP"
Y200: library part OSC_KYOCERA, "Osc, Kyocera"

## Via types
v1: diameter 25, hole 12, Top Layer to Bottom Layer, 164 vias
v2: diameter 20, hole 12, Top Layer to Bottom Layer, 3 vias
v3: diameter 25, hole 12, Top Layer to Bottom Layer, tented top, 3 vias
v4: diameter 25, hole 12, Top Layer to Bottom Layer, tented bottom, 1 vias

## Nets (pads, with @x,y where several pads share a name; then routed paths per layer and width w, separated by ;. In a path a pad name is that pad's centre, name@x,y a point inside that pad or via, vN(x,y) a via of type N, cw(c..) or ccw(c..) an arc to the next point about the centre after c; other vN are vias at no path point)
1_A/GNDB: RA20-1.1 RA20-2.1 U300.14 | length 97
  Top Layer w20: RA20-1.1@573,679 v1(597,679) U300.14@637,679
  Bottom Layer w20: RA20-2.1@564,679 v1(597,679)
1_REB/DE: U200.11 U300.6 U300.7 | length 684.1
  Top Layer w10: v1@1240,936.42 U200.11@1632.68,936.42
  Top Layer w15: U300.6@1026.12,831 1026.12,876.12 U300.7@1029,879 ; U300.7@1026.12,881 1103,881 v1@1104,882
  Bottom Layer w15: v1(1106,881) 1178,881 v1@1243,946
  other v1: 1241,943
1_RXD: U200.13 U300.5 | length 678.8
  Top Layer w10: U300.5@1043,785 1078.19,785 1150.86,857.68 U200.13@1691.73,857.68
1_TD1: T300.3 U300.1 | length 462.2
  Top Layer w15: 965,533 960,538 960,547 969,556 1035.24,556 1039.12,559.88 U300.1@1039.12,581 ; 970,532 1065,532 1072,525 1072,516 1065,509 969,509 963,503 963,493 969,487 998,487 1029,456 T300.3@1029,451 ; U300.1@1026.12,581 U300.1@1034,581 ; T300.3@1037,455 T300.3@1037,459
  Top Layer w20: T300.3@1026.12,447.88 T300.3@1029,445
1_TD2: T300.1@1037.35,246 U300.2 | length 462.7
  Top Layer w10: U300.2@1026.12,631 U300.2@1041,631
  Top Layer w15: U300.2@1043,633 1074,633 1102,605 1102,290 T300.1@1058,246
1_TXD: U200.12 U300.8 | length 596.2
  Top Layer w10: U300.8@1042,930 1072,930 1085.27,916.73 U200.12@1632.68,916.73
1_VLDO/DEM: RA16-1.1 U300.10 | length 69.9
  Top Layer w20: RA16-1.1@585,882 U300.10@654.88,882
1_Y/VLDO: RA17-1.1 RA17-2.1 U300.11 | length 119.3
  Top Layer w20: RA17-1.1@575,832 576,831 U300.11@665.88,831
  Bottom Layer w20: RA17-2.1@578,832 v1(606,832)
1_Z/A: RA18-1.1 RA18-2.1 U300.12 | length 150
  Top Layer w20: RA18-1.1@561,781 U300.12@665.88,781
  Bottom Layer w20: RA18-2.1@564,772 580,772 590,782 v1(605,782)
2_A/GNDB: RB20-1.1 RB20-2.1 U301.14 | length 118.5
  Top Layer w20: RB20-1.1@578,1699 582,1695 U301.14@663.88,1695
  Bottom Layer w20: RB20-2.1@575,1696 v1(606,1696)
2_REB/DE: U200.27 U301.6 U301.7 | length 2003.9
  Top Layer w10: U301.7@1032,1892 1312,1892 1381,1823 1381,1810 ; 1381,1815 1381,1015 v1@1421,975 ; v1@1889,950 1895.1,956.1 U200.27@1967.32,956.1
  Top Layer w20: U301.6@1026.12,1847 U301.7@1026.12,1894.88
  Bottom Layer w10: v1(1419,977) 1576,820 1576,819 1616,779 1652,779 1822,949 v1@1894,949
  other v1: 1889,948
2_RXD: U200.22 U301.5 | length 1932.8
  Top Layer w10: U301.5@1026.12,1797 1055,1797 1078,1820 v1@1115,1820 ; v1@1376,815 1376,806 1512,670 1728,670 1868.9,810.9 U200.22@1868.9,857.68
  Bottom Layer w10: v1@1118,1818 1124,1824 1221,1824 1322,1723 1322,963 1372,913 v1@1372,821
  other v1: 1373,819 1118,1820
2_TD1: T301.3 U301.1 | length 426.9
  Top Layer w15: T301.3@1018,1486 1018,1496 1031,1509 1090,1509 1096,1515 1096,1526 1090,1532 987,1532 981,1538 981,1546 986,1551 1091,1551 1098,1558 1098,1567 1092,1573 1055,1573 U301.1@1044,1584
2_TD2: T301.1@1037.35,1271 U301.2 | length 427.8
  Top Layer w15: T301.1@1041,1277 1066,1277 1120,1331 1120,1591 U301.2@1073,1638
2_TXD: U200.21 U301.8 | length 2006.1
  Top Layer w10: U301.8@1026.12,1947 1245,1947 v1@1246,1948 ; v1@1418,820 1418,802 1536,684 1719,684 1849.21,814.21 U200.21@1849.21,857.68
  Bottom Layer w10: v1@1253,1944 1360,1837 1360,971 1418,913 v1(1418,822)
  other v1: 1249,1944
2_VLDO/DEM: RB16-1.1 U301.10 | length 85.2
  Top Layer w20: RB16-1.1@596,1934 633,1897 U301.10@665.88,1897
  other v1: 614,1915
2_Y/VLDO: RB17-1.1 RB17-2.1 U301.11 | length 150.3
  Top Layer w20: RB17-1.1@571,1873 597,1873 622,1848 647,1848 648,1847 U301.11@665.88,1847
  Bottom Layer w20: RB17-2.1@570,1877 596.93,1876 v1@609,1863
  other v1: 609,1862
2_Z/A: RB18-1.1 RB18-2.1 U301.12 | length 121.7
  Top Layer w10: RB18-1.1@575,1795 RB18-1.1@576,1796 ; RB18-1.1@586,1797 U301.12@665.88,1797
  Bottom Layer w10: v1(606,1795) v1@610,1795
  Bottom Layer w15: RB18-2.1@573.59,1797 v1@610,1797
A1: P300.4 R301.1 RA18-2.2 RA20-1.2 TVS303.2 | length 585.9
  Top Layer w20: v1@282,743 282,691 323.79,649.21 P300.4@419.84,649.21 ; P300.4@482,660 504,682 RA20-1.2@512,682
  Bottom Layer w15: TVS303.2@359.69,661.6 361.29,660 442,660 v1@477,625 ; v1@477,617 v1(477,620) v1@477,625 ; RA18-2.2@517.41,770 517.41,711.23 477,670.82 v1@477,625
  Bottom Layer w20: v1@282,744 R301.1@282,781.41
  other v1: 283,741
A2: P301.4 R304.1 RB18-2.2 RB20-1.2 TVS302.2 | length 580.1
  Top Layer w10: P301.4@458,1702 P301.4@464,1696
  Top Layer w20: v1(239,1815) 268,1815 P301.4@370,1713 ; P301.4@464,1696 RB20-1.2@531.41,1696
  Bottom Layer w20: v1(239,1815) R304.1@239,1850 ; TVS302.2@341,1716 342,1715 450,1715 v1(488,1677) 521.41,1710.41 RB18-2.2@521.41,1796
B1: P300.3 R300.1 R302.2 TVS303.1 U300.13 | length 685.8
  Top Layer w15: P300.3@464,741 469,736 P300.3@474,736 ; P300.3@470,754 P300.3@477,761 ; P300.3@484,733 485,732 U300.13@654.88,732
  Bottom Layer w15: R300.1@324,781 324,771 TVS303.1@352,743 ; TVS303.1@356.69,743.4 352.4,743.4 TVS303.1@352,743 ; TVS303.1@359.69,736.4 361.09,735 378,735 423,780 v1@477,780 ; TVS303.1@379,738 357,738 TVS303.1@352,743 ; R302.2@401,554 R302.2@399.41,554 361,554 304,611 304,695 TVS303.1@352,743
  other v1: 479,780
B2: P301.3 R303.2 R305.1 TVS302.1 U301.13 | length 696.1
  Top Layer w10: v1@486,1779 520,1745 U301.13@651.88,1745
  Bottom Layer w20: R305.1@276,1862 276,1844 330,1790 TVS302.1@331,1790 ; TVS302.1@337,1790 TVS302.1@331,1790 ; R303.2@390.41,1613 359,1613 293,1679 293,1752 TVS302.1@331,1790 ; v1(486,1780) 471,1795 336,1795 TVS302.1@331,1790
BOOT0: R209.2 U200.44 | length 104.3
  Top Layer w10: v1(1760,1145) 1770.07,1155.07 1770.18,1155.14 1770.18,1170 1770.38,1192.32 U200.44@1770.47,1202.17
  Bottom Layer w10: R209.2@1735,1112.5 R209.2@1735,1115.59 1735,1120 v1(1760,1145)
BOOT1: R211.2 U200.20 | length 103.7
  Top Layer w10: U200.20@1829.53,857.68 v1@1829.53,900
  Bottom Layer w10: v1(1830,910) 1830,887.5 R211.2@1857.5,860
CLK_M: R402.2 U200.5 Y200.3 | length 580
  Top Layer w10: U200.5@1622.83,1054.53 U200.5@1632.68,1054.53 1660,1054.53 1680,1074.53 1680,1145 1650,1175 1650,1265.16 Y200.3@1649.53,1285.63 1695,1331.1 1695,1385 1720,1410 1854.41,1410 R402.2@1857.5,1410
EP2: U100.30 U100.35 U100.36 U100.37
GND_F: P200.A16 P200.A17 P200.A18
GND_S: C100.2 C101.2 C102.2 C200.2 C201.2 C202.2 C203.2 C204.2 C205.2 C206.2 C207.2 C300.1 C303.1 C306.2 C307.2 C310.1 C311.1 C400.2 C401.2 C402.2 C403.2 C404.2 C405.2 LED200.2 LED201.2 P200.A2 P200.A4 P200.A9 P200.A10 P200.B2 P200.B4 P200.B7 P200.B8 P200.B10 P201.3 P201.5 P201.9 P400.5 P400.6 P400.7 P400.8 P400.9 P400.10 R102.1 R209.1 R211.1 R213.1 TP101.1 U100.5 U100.6 U100.7 U100.21 U100.22 U100.23 U100.24 U100.25 U100.26 U100.27 U100.31 U100.38 U100.39 U100.40 U100.41 U100.42 U200.8 U200.23 U200.35 U200.47 U300.3 U301.3 U400.5 U400.13 U400.14 U400.15 U400.16 Y200.2 | length 3753.3
  Top Layer w10: v1(1570,1005) 1579.53,995.47 U200.8@1622.83,995.47 ; v1(1580,760) 1575,760 1578,763 1582.28,758.72 LED200.2@1582.28,715 ; U200.47@1711.42,1192.32 1711.42,1216.42 v1(1735,1240) ; C206.2@1795,1270 v1(1800,1275) ; C207.2@1795,1335 v1(1795,1380) ; v1(1880,780) 1888.58,788.58 U200.23@1888.58,847.83 ; U200.35@1977.17,1113.58 2027.5,1113.58 2035,1106.08 v1(2035,1105) ; C403.2@2099,2029 2113.43,2014.57 U400.5@2113.43,1969.06 U400.13@2113.43,1910 ; v1(2375,1835) 2375,1853.82 2405,1883.82 P400.5@2435.82,1883.82
  Top Layer w15: U300.3@1046.59,682 v3@1184,682 ; U301.3@1049,1694 v1@1167,1694 ; C200.2@1520,1316.54 1520,1280 v1(1522,1278) ; v1@1524.63,1285.63 Y200.2@1590.47,1285.63 ; C204.2@1550,1205 1577.5,1177.5 1580,1177.5 v1(1580,1180) ; v1@2082.5,1736.54 C404.2@2082.5,1775 ; v1@2082.5,1740 v1(2085,1735) ; C401.2@2307.5,2000 v1@2345,2000 ; C402.2@2312.5,1800 v4(2345,1800)
  Top Layer w20: v1(1219,222) P201.3@1219,278 ; v1@1269,224 v1(1269,220) P201.5@1269,278 ; v1@1369,216.5 P201.9@1369,278 ; v1(1896,1379) 1896,1376 1897,1377 1902.28,1371.72 LED201.2@1902.28,1340 ; v1@2065,2030 C403.2@2094.41,2030 ; v1@2250.71,1105.71 v1(2250,1105) P200.B10@2455,1105 ; v1(2255,815) 2290,815 2315,790 P200.B2@2450.63,790 ; v1(2255,855) 2270,870 P200.B4@2450.63,870 ; C400.2@2340,2102.5 v1(2340,2135) ; P200.B7@2460.63,987.6 2267.4,987.6 v1(2250,1005) 2271.97,1026.97 P200.B8@2460.63,1026.97
  Bottom Layer w10: v1(1364.5,216.5) R213.1@1364.5,249 ; v1(1570,1005) v1@1570,1007.5 ; R209.1@1735,1067.5 1757.5,1067.5 v1(1770,1055) ; v1@1877.5,782.5 v1(1880,780) ; v1(1885,905) 1885,877.5 R211.1@1902.5,860 ; v1@2032.5,1102.5 v1(2035,1105)
  Bottom Layer w15: C307.2@1130.59,389 1130.59,360.41 1219,272 v1@1219,223 ; v1@1570,1007.5 C203.2@1605,1007.5 ; C202.2@1770,1017.5 v1(1770,1055) ; U100.38@1820.34,455.36 U100.38@1829.59,464.61 ; v1@1877.5,782.5 1877.5,820 ; C205.2@1990,1102.5 v1@2032.5,1102.5
  Bottom Layer w20: v1(2255,815) 2290,815 2315,790 P200.A2@2450.63,790 ; v1(2255,855) 2270,870 P200.A4@2440.12,870 ; P200.A10@2450,1105 v1(2250,1105) 2290,1065 P200.A9@2455.99,1065
  other v1: 1719,203 1764,203 1719,238 1764,238 1809,280.5 1846.5,280.5 1639,283 1806.5,370.5 1846.5,370.5 1168,1692 2545,1895 2545,1935 2545,1975 2345,1995 2060,2030
  other v3: 1182,681
GNDB: C301.1 C302.1 C305.2 C308.1 C309.1 C312.1 C313.2 C314.1 C319.1 C320.1 C325.1 C327.1 J300.2 J300.3 P300.6 P301.6 P301.7 P301.8 RA20-2.2 RB20-2.2 T300.5 T301.5 TVS300.3 TVS301.3 TVS302.3 TVS303.3 U300.9 U300.15 U301.9 U301.15 | length 1251.7
  Top Layer w15: C302.1@523,1639 531,1647 ; C320.1@524,632 v1@607,632 ; C305.2@614,1369 C305.2@617,1372 ; C305.2@616.59,1373 616.59,1404.59 v1(619,1407) ; U300.15@654.88,632 v1@607,632 ; U300.15@665.88,631 608,631 v1@607,632 ; T300.5@673,341 T300.5@674,340
  Top Layer w20: 531,1647 v1(610,1644) U301.15@664.88,1644 ; v1@534,1046 527.41,1039.41 527.41,989.59 C325.1@550,989.59 ; 537,2025.59 v2(537,2080) ; C305.2@617,1372 T301.5@679.65,1372 ; C313.2@618,346 T300.5@679.65,346 ; U301.9@651.88,1945 v2@651.88,1973.12 ; U300.9@654.88,932 v1@654.88,966.88
  Top Layer w25: P301.8@419.84,1318.84 P301.7@419.84,1413.94 P301.6@419.84,1512.36 ; v1(674,306) T300.5@674,340
  Bottom Layer w15: v1@370,1953 TVS300.3@437.31,1953 ; v1(383,1757) 385,1755 TVS302.3@429.31,1755 ; v1@396.31,703 TVS303.3@440,703 ; v1@399,900 TVS301.3@470.31,900 ; TVS303.3@443,697 TVS303.3@462.31,697 ; TVS301.3@481,901 TVS301.3@491,891 ; RA20-2.2@574.59,631 602,631 v1@603,630
  Bottom Layer w20: RB20-2.2@578,1645 580,1647 v1(610,1644)
  other v1: 489,425 606,630 397,703 400,900 655,969 533,1043 485,1292 485,1386 483,1484 370,1952
  other v2: 651,1977
IIC_SCL: P200.B5 R201.1 R205.1 | length 808.6
  Top Layer w10: R201.1@2172.5,855 R201.1@2175.59,855 v1(2210,855) 2210,863.86 2251.14,905 P200.B5@2445,905
  Bottom Layer w10: R205.1@1860,1042.5 R205.1@1860,1039.41 1860,1010 1930,940 2012.5,940 2062.5,890 2062.5,837.5 2077.5,822.5 2187.5,822.5 2210,845 v1(2210,855)
IIC_SDA: P200.B6 R200.1 R206.1 | length 830.5
  Top Layer w10: v1(2090,1065) 2117.5,1065 2172.5,1010 2172.5,925 R200.1@2175.59,925 2220,925 2240,945 2460,945 P200.B6@2470,955
  Mid-Layer 3 w10: v1(1815,1010) 1825,1020 2045,1020 v1(2090,1065)
  Bottom Layer w10: v1(1815,1010) R206.1@1815,1039.41 R206.1@1815,1042.5
INT: P200.B9 U200.39 | length 693.7
  Top Layer w10: U200.39@1868.9,1202.17 1868.9,1165 1883.9,1150 1920,1150 1955,1185 2035,1185 2155,1065 P200.B9@2455,1065
ISO_24V: J300.1 P300.7 P300.8
  other v1: 404,194 446,194 364,195 492,196
LED_G: R210.2 U200.10 | length 209.2
  Top Layer w10: U200.10@1622.83,956.1 1678.9,956.1 v1(1680,955)
  Bottom Layer w10: v1(1640,820) 1680,860 v1(1680,955)
LED_R: R212.2 U200.38 | length 82.4
  Top Layer w10: U200.38@1888.58,1202.17 1888.58,1261.58 1897.5,1270.5 R212.2@1897.5,1280 R212.2@1897.5,1280.91
NetC301_2: C301.2 C320.2 C327.2 U300.16 | length 146.9
  Top Layer w15: C320.2@520,582 U300.16@654.88,582
  Top Layer w20: 625,583 U300.16@637,583
NetC302_2: C302.2 C308.2 C309.2 U301.16 | length 142.9
  Top Layer w20: C302.2@516,1591 519,1588 v1(615,1588) 619,1592 U301.16@656,1592
NetC400_1: C400.1 L400.1 R403.2
  other v1: 2362,2064
NetC401_1: C401.1 R401.2 U400.1 | length 121.6
  Top Layer w15: 2190.26,1963.09 2249.41,1963.09 ; C401.1@2249.41,2000 2249.41,1963.09 ; R401.2@2267.5,1945 2249.41,1963.09
NetC402_1: C402.1 R400.2 U400.12 | length 154
  Top Layer w10: U400.12@2184.29,1850.94 2210.94,1850.94 2225,1865 R400.2@2267.5,1865
  Top Layer w15: C402.1@2267.5,1800 R400.2@2267.5,1865
NetD300_1: D300.1 T301.6 | length 125.9
  Top Layer w20: v1@656,1222 674,1240 T301.6@674,1274
  Bottom Layer w20: v1(657,1219) 657,1243 D300.1@687,1273
NetD301_1: D301.1 T301.4 | length 103.2
  Top Layer w10: T301.4@679.65,1472 T301.4@679.65,1485.35
  Top Layer w20: v1@654,1511 T301.4@679.65,1485.35
  Bottom Layer w20: v1(656,1513) 656,1499 D301.1@684,1471
NetD302_1: D302.1 T300.4 | length 113.1
  Top Layer w20: v1@662,495 679.65,477.35 T300.4@679.65,446
  Bottom Layer w20: v1@663,497 681.83,478.17 D302.1@681.83,448
  other v1: 662,493
NetD303_1: D303.1 T300.6 | length 118.8
  Top Layer w20: v1@660,195 679.65,214.65 T300.6@679.65,246
  Bottom Layer w20: v1@658,198 683.83,223.83 D303.1@683.83,247
  other v1: 657,197
NetLED200_1: LED200.1 R210.1 | length 35.4
  Top Layer w10: LED200.1@1617.72,720 1620,722.28 R210.1@1620,754.41
NetLED201_1: LED201.1 R212.1 | length 62
  Top Layer w10: LED201.1@1937.72,1340 1937.72,1284.78 R212.1@1942.5,1280
NetNT201_A: 
NetP201_7: P201.7 R213.2 | length 83
  Top Layer w10: v1(1319,218) P201.7@1319,278
  Bottom Layer w10: v1(1319,218) R213.2@1319,240.99
NetP300_5: P300.5 R302.1 | length 39
  Top Layer w15: P300.5@453,542 P300.5@453.59,542.59
  Bottom Layer w15: R302.1@456,553 v1@483,526
  other v1: 487,525
NetP301_5: P301.5 R303.1 | length 40.6
  Bottom Layer w20: R303.1@444,1612 472,1584 v1(473,1584)
NetP400_1: P400.1 R403.1 | length 69.3
  Top Layer w15: v1@2376,2009 2398.82,1986.18 P400.1@2435.82,1986.18
  other v1: 2377,2003
NetP400_2: P400.2 R401.1 | length 108.6
  Top Layer w15: R401.1@2334.2,1943.83 2368.24,1943.83 2385,1960.59 P400.2@2435.82,1960.59
NetP400_3: P400.3 R400.1 | length 132.7
  Top Layer w15: R400.1@2332.5,1867.5 2400,1935 P400.3@2434.76,1935
  Top Layer w20: R400.1@2332.5,1865 R400.1@2332.5,1867.5
NetR100_1: R100.1 U100.4 | length 92.1
  Top Layer w10: U100.4@1921.91,513 v1(1974,513)
  Bottom Layer w10: R100.1@1934,515.5 v1@1974,515.5
NetR101_1: R101.1 R102.2 U100.9 | length 154.8
  Top Layer w10: U100.9@1748.69,565.2 1748.69,533.31 v1(1749,533)
  Bottom Layer w10: R101.1@1721.5,573 1721.5,548 1736.5,533 v1(1749,533) 1766.5,533 1781.5,548 R102.2@1781.5,573
NetR202_2: R202.2 U200.14 | length 631.9
  Top Layer w10: v1(1702.5,785) 1702.5,786.08 1711.42,795 U200.14@1711.42,847.83
  Mid-Layer 3 w10: v1(1702.5,785) 1787.5,870 1925,870 1955,900 1955,970 1982.5,997.5 2062.5,997.5 v1(2090,1025)
  Bottom Layer w10: v1(2090,1025) R202.2@2124.41,1025 R202.2@2127.5,1025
